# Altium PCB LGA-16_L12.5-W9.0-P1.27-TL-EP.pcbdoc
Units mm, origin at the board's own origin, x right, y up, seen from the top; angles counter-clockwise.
Board outline 26.21 x 21.85 mm, 2 copper layers (Top Layer, Bottom Layer), stack 0 mm thick; 1 components, 0 nets, 17 pads, 0 vias.
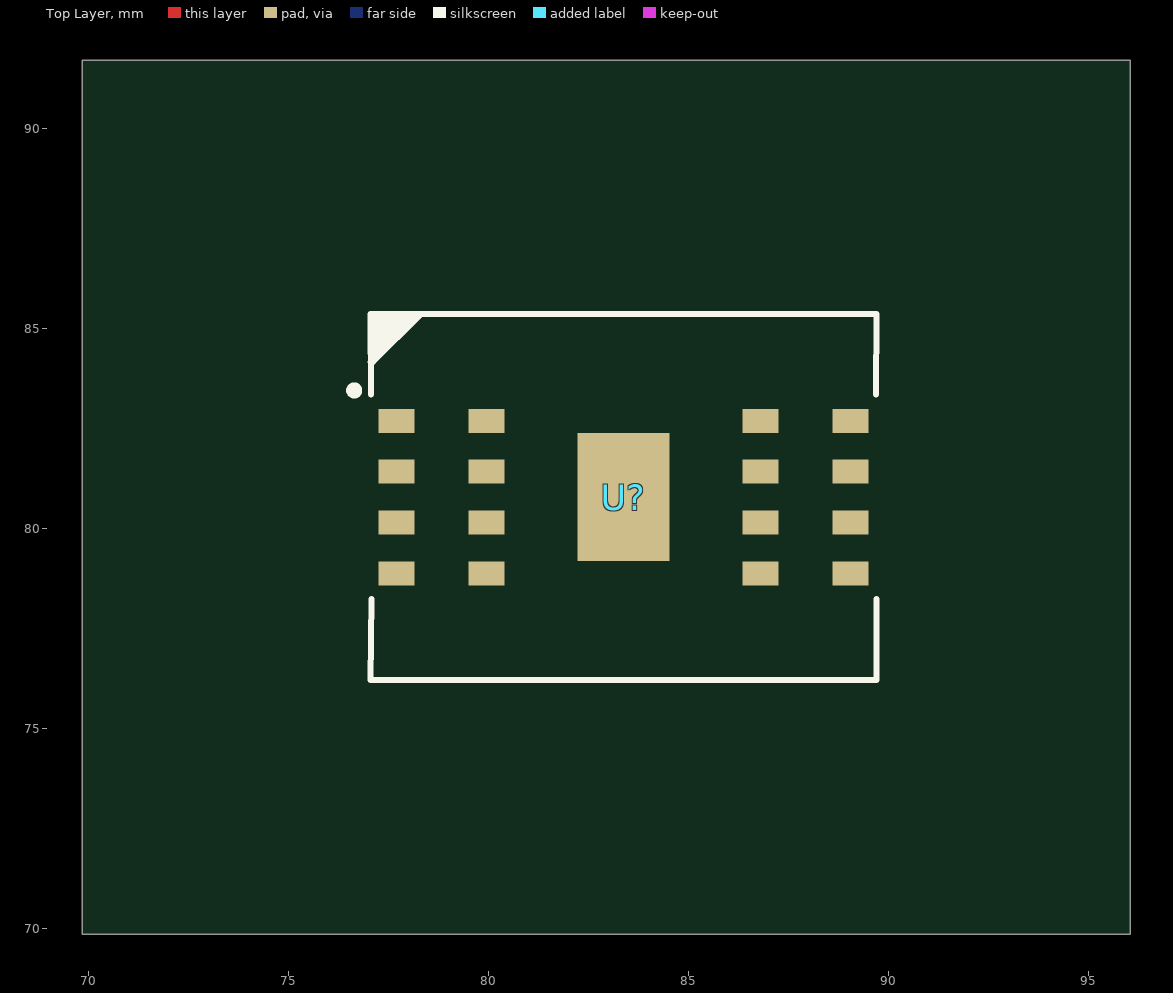
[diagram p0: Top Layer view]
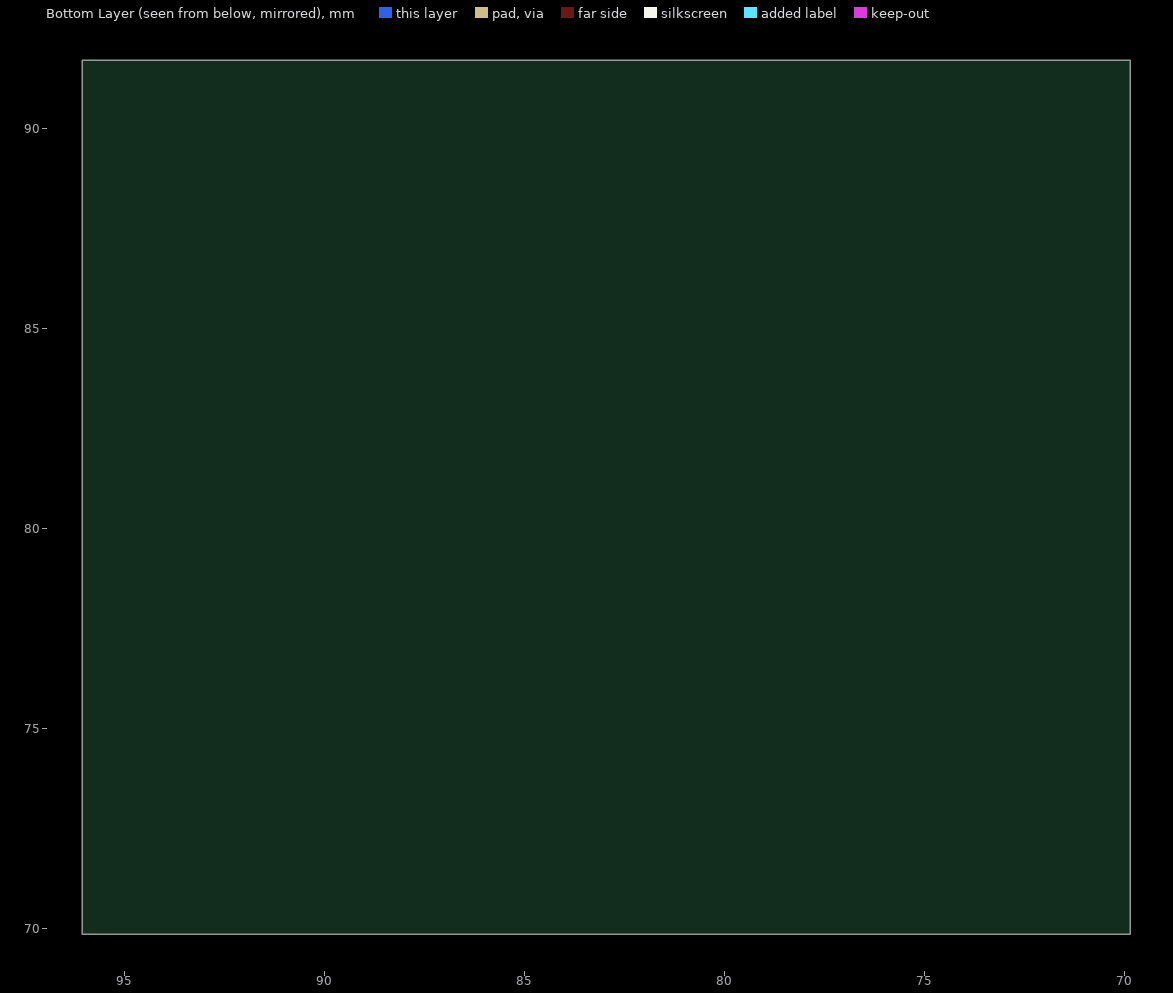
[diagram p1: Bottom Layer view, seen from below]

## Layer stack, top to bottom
Top Layer: signal copper (thickness not stored)
Bottom Layer: signal copper (thickness not stored)

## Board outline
96.061,69.85 69.85,69.85 69.85,91.703 96.061,91.703

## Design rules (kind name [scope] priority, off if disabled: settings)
PasteMaskExpansion "Paste Mask Expansion" [All] p1: expansion=0
SolderMaskExpansion "Solder Mask Expansion" [IsVia] p1: expansion=-25.4 istentingtop=TRUE
SolderMaskExpansion "Solder Mask Expansion" [All] p2: expansion=0.051 istentingtop=FALSE

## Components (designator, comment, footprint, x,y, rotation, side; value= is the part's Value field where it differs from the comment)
U? "" LGA-16_L12.5-W9.0-P1.27-TL-EP 83.385,80.776 r0 top

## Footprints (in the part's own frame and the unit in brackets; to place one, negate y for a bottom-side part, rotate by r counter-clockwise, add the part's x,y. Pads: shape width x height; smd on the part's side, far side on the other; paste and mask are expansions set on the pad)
LGA-16_L12.5-W9.0-P1.27-TL-EP [mm]
  rect 0.9x0.6 smd: 1(-5.675,1.905) 1(-3.425,1.905) 2(-5.675,0.635) 2(-3.425,0.635) 3(-5.675,-0.635) 3(-3.425,-0.635) 4(-5.675,-1.905) 4(-3.425,-1.905) 5(3.425,-1.905) 5(5.675,-1.905) 6(3.425,-0.635) 6(5.675,-0.635) 7(3.425,0.635) 7(5.675,0.635) 8(3.425,1.905) 8(5.675,1.905)
  rect 2.3x3.2 smd: 9(0,0)
  silkscreen extent -6.83,-4.58 6.33,4.58

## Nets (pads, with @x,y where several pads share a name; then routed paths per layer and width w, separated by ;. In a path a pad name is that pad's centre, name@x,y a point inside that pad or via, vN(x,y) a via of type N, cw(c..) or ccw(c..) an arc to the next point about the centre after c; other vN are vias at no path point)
pads on no net: U?.1 U?.2 U?.3 U?.4 U?.5 U?.6 U?.7 U?.8 U?.9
